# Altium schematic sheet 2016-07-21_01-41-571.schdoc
size 313 x 134 mm; SheetNumber: 1; SheetTotal: 1
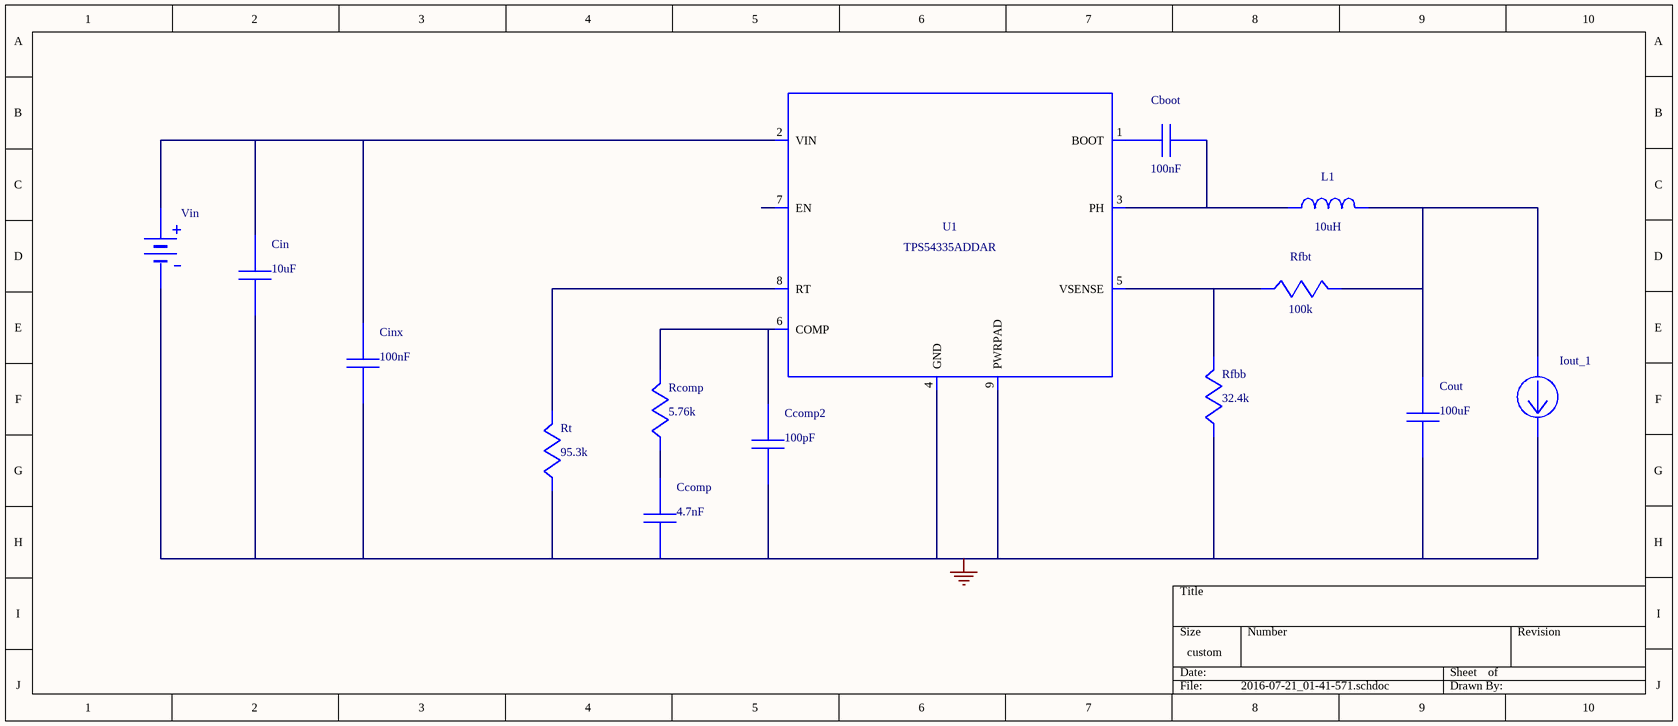
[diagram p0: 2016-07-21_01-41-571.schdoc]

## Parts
Cboot  value 100nF  (hidden comment: C0805C104K5RACTU)
Ccomp  value 4.7nF  (hidden comment: CC0805KRX7R9BB472)
Ccomp2  value 100pF  (hidden comment: CC0805JRNPO9BN101)
Cin  value 10uF  (hidden comment: GRM31CR61E106KA12L)
Cinx  value 100nF  (hidden comment: C0805C104K5RACTU)
Cout  value 100uF  (hidden comment: GRM31CR60J107ME39L)
Iout_1  WB_CURRENT_LOAD  (value not drawn)
L1  value 10uH  (hidden comment: SRU1038-100Y)
Rcomp  value 5.76k  (hidden comment: CRCW04025K76FKED)
Rfbb  value 32.4k  (hidden comment: CRCW040232K4FKED)
Rfbt  value 100k  (hidden comment: CRCW0402100KFKED)
Rt  value 95.3k  (hidden comment: CRCW040295K3FKED)
U1  TPS54335ADDAR
Vin  WB_BATTERY  (value not drawn)

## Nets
0: Ccomp.2 Ccomp2.2 Cin.2 Cinx.2 Cout.2 Iout_1.2(-) Rfbb.2 Rt.2 U1.4(GND) U1.9(PWRPAD) Vin.2(-)
NetCboot_1: Cboot.1 U1.1(BOOT)
NetCboot_2: Cboot.2 L1.1 U1.3(PH)
NetCcomp2_1: Ccomp2.1 Rcomp.1 U1.6(COMP)
NetCcomp_1: Ccomp.1 Rcomp.2
NetCin_1: Cin.1 Cinx.1 U1.2(VIN) Vin.1(+)
NetCout_1: Cout.1 Iout_1.1(+) L1.2 Rfbt.1
NetRfbb_1: Rfbb.1 Rfbt.2 U1.5(VSENSE)
NetRt_1: Rt.1 U1.8(RT)

Not connected (* = marked no-connect by the designer): U1 7(EN)

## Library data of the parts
Cboot Cinx = C0805C104K5RACTU: Manufacturer Name: Kemet
Ccomp = CC0805KRX7R9BB472: CC0805KRX7R9BB47; Manufacturer Name: Yageo America
Ccomp2 = CC0805JRNPO9BN101: CC0805JRNPO9BN10; Manufacturer Name: Yageo America
Cin = GRM31CR61E106KA12L: GRM31CR61E106KA1; Manufacturer Name: MuRata
Cout = GRM31CR60J107ME39L: GRM31CR60J107ME3; Manufacturer Name: MuRata
L1 = SRU1038-100Y: Manufacturer Name: Bourns
Rcomp = CRCW04025K76FKED: Manufacturer Name: Vishay-Dale
Rfbb = CRCW040232K4FKED: Manufacturer Name: Vishay-Dale
Rfbt = CRCW0402100KFKED: Manufacturer Name: Vishay-Dale
Rt = CRCW040295K3FKED: Manufacturer Name: Vishay-Dale
U1 = TPS54335ADDAR: Manufacturer Name: Texas Instruments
